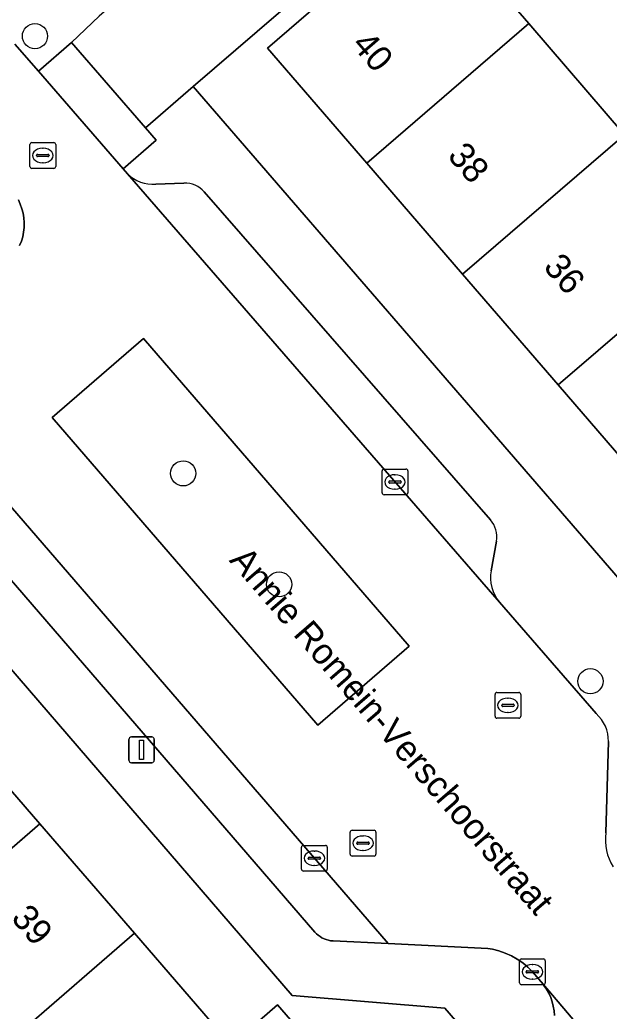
# Model space of a CAD drawing. Extents: x 160304 to 160955, y 383684 to 384161.
# Drawn here: x 160439.02 to 160461.92, y 384055.67 to 384094.2 of the extents above; entities that cross this region are included whole.
import ezdxf

# ---------------------------------------------------------------- set-up
doc = ezdxf.new("R2010")
doc.units = 0
for name, color, linetype in [('IMGEO_Boom', 7, 'Continuous'), ('IMGEO_Erf', 7, 'Continuous'), ('IMGEO_Kolk', 7, 'Continuous'), ('IMGEO_Lichtmast', 7, 'Continuous'), ('IMGEO_Openbare_ruimte_label', 7, 'Continuous'), ('IMGEO_Pand', 7, 'Continuous'), ('IMGEO_Pand_nummerreeks', 7, 'Continuous'), ('IMGEO_Parkeervlak_open', 7, 'Continuous'), ('IMGEO_Rijbaan_lokaal_open', 7, 'Continuous'), ('IMGEO_Rioolput', 7, 'Continuous'), ('IMGEO_Voetpad_open', 7, 'Continuous')]:
    doc.layers.add(name, color=color, linetype=linetype)

msp = doc.modelspace()

# ---------------------------------------------------------------- linework, layer by layer
at = {"layer": 'IMGEO_Boom'}
for centre in [(160439.61, 384093.564), (160445.372, 384076.571), (160449.097, 384072.258), (160461.195, 384068.492)]:
    msp.add_circle(centre, 0.489, dxfattribs=at)
at = {"layer": 'IMGEO_Erf'}
for points in [[(160480.535, 384052.567), (160476.806, 384056.888), (160473.083, 384061.203), (160469.356, 384065.523), (160465.516, 384069.973), (160467.284, 384071.499), (160463.67, 384075.687), (160459.939, 384080.012), (160456.229, 384084.312), (160452.508, 384088.624), (160448.645, 384093.101), (160454.74, 384098.361), (160454.335, 384098.831), (160457.615, 384101.658), (160457.542, 384101.745), (160445.759, 384091.611), (160464.179, 384070.303), (160464.114, 384064.194), (160482.27, 384043.068)], [(160458.201, 384094.743), (160458.796, 384094.053), (160462.523, 384089.733), (160466.243, 384085.421), (160468.493, 384082.814), (160471.638, 384085.527), (160473.112, 384083.818), (160474.901, 384081.745), (160471.757, 384079.032), (160473.809, 384076.654), (160475.061, 384077.691), (160478.712, 384073.459), (160478.133, 384072.959), (160481.824, 384068.681), (160485.546, 384064.367), (160483.121, 384062.275), (160486.83, 384057.977)]]:
    msp.add_lwpolyline(points, dxfattribs=at)
msp.add_lwpolyline([(160431.035, 384077.833), (160428.673, 384075.798), (160432.433, 384071.455), (160436.115, 384067.202), (160439.796, 384062.95), (160443.478, 384058.697), (160447.238, 384054.354), (160449.036, 384055.91), (160453.642, 384050.589), (160458.283, 384045.229), (160461.083, 384041.994), (160464.755, 384045.129), (160455.536, 384055.791), (160449.608, 384056.274)], close=True, dxfattribs=at)
at = {"layer": 'IMGEO_Kolk'}
for p, q in [((160453.1, 384075.811), (160453.1, 384076.663)), ((160453.175, 384076.737), (160454.027, 384076.737)), ((160453.588, 384076.517), (160453.613, 384076.517)), ((160454.101, 384076.663), (160454.101, 384075.811)), ((160453.359, 384076.231), (160453.359, 384076.243)), ((160453.797, 384076.194), (160453.399, 384076.194)), ((160453.402, 384076.28), (160453.8, 384076.28)), ((160453.843, 384076.243), (160453.843, 384076.231)), ((160454.027, 384075.737), (160453.175, 384075.737)), ((160453.611, 384075.957), (160453.586, 384075.957)), ((160449.967, 384061.188), (160449.967, 384062.04)), ((160450.042, 384062.114), (160450.894, 384062.114)), ((160450.455, 384061.894), (160450.48, 384061.894)), ((160450.968, 384062.04), (160450.968, 384061.188)), ((160450.226, 384061.608), (160450.226, 384061.62)), ((160450.664, 384061.571), (160450.266, 384061.571)), ((160450.269, 384061.657), (160450.667, 384061.657)), ((160450.71, 384061.62), (160450.71, 384061.608)), ((160450.894, 384061.114), (160450.042, 384061.114)), ((160450.478, 384061.334), (160450.453, 384061.334)), ((160458.44, 384056.772), (160458.44, 384057.624)), ((160458.515, 384057.698), (160459.367, 384057.698)), ((160459.441, 384057.624), (160459.441, 384056.772)), ((160458.699, 384057.192), (160458.699, 384057.204)), ((160458.742, 384057.241), (160459.14, 384057.241)), ((160458.928, 384057.478), (160458.953, 384057.478)), ((160459.183, 384057.204), (160459.183, 384057.192)), ((160459.137, 384057.155), (160458.739, 384057.155)), ((160458.951, 384056.918), (160458.926, 384056.918)), ((160459.367, 384056.698), (160458.515, 384056.698))]:
    msp.add_line(p, q, dxfattribs=at)
for points in [[(160453.1, 384075.811), (160453.1, 384076.663)], [(160453.175, 384076.737), (160454.027, 384076.737)], [(160454.101, 384076.663), (160454.101, 384075.811)], [(160454.027, 384075.737), (160453.175, 384075.737)], [(160449.967, 384061.188), (160449.967, 384062.04)], [(160450.042, 384062.114), (160450.894, 384062.114)], [(160450.968, 384062.04), (160450.968, 384061.188)], [(160450.894, 384061.114), (160450.042, 384061.114)], [(160458.44, 384056.772), (160458.44, 384057.624)], [(160458.515, 384057.698), (160459.367, 384057.698)], [(160459.441, 384057.624), (160459.441, 384056.772)], [(160459.367, 384056.698), (160458.515, 384056.698)]]:
    msp.add_lwpolyline(points, dxfattribs=at)
for centre, radius, start, end in [((160453.177, 384076.661), 0.0765, 91.552, 178.448), ((160453.177, 384076.661), 0.0765, 91.552, 178.448), ((160454.025, 384076.661), 0.0765, 1.552, 88.448), ((160454.025, 384076.661), 0.0765, 1.552, 88.448), ((160453.399, 384076.24), 0.0403, 85.8775, 175.7526), ((160453.396, 384076.23), 0.0366, 178.938, 274.7102), ((160453.8, 384076.237), 0.043, 264.8664, 352.4533), ((160453.804, 384076.242), 0.0386, 1.7309, 96.639), ((160453.177, 384075.813), 0.0765, 181.552, 268.448), ((160453.177, 384075.813), 0.0765, 181.552, 268.448), ((160454.025, 384075.813), 0.0765, 271.552, 358.448), ((160454.025, 384075.813), 0.0765, 271.552, 358.448), ((160450.044, 384062.038), 0.0765, 91.552, 178.448), ((160450.044, 384062.038), 0.0765, 91.552, 178.448), ((160450.892, 384062.038), 0.0765, 1.552, 88.448), ((160450.892, 384062.038), 0.0765, 1.552, 88.448), ((160450.266, 384061.617), 0.0403, 85.8775, 175.7526), ((160450.263, 384061.607), 0.0366, 178.938, 274.7102), ((160450.667, 384061.614), 0.043, 264.8664, 352.4533), ((160450.671, 384061.619), 0.0386, 1.7309, 96.639), ((160450.044, 384061.19), 0.0765, 181.552, 268.448), ((160450.044, 384061.19), 0.0765, 181.552, 268.448), ((160450.892, 384061.19), 0.0765, 271.552, 358.448), ((160450.892, 384061.19), 0.0765, 271.552, 358.448), ((160458.517, 384057.622), 0.0765, 91.552, 178.448), ((160458.517, 384057.622), 0.0765, 91.552, 178.448), ((160459.365, 384057.622), 0.0765, 1.552, 88.448), ((160459.365, 384057.622), 0.0765, 1.552, 88.448), ((160458.739, 384057.201), 0.0403, 85.8775, 175.7526), ((160458.736, 384057.191), 0.0366, 178.938, 274.7102), ((160459.14, 384057.198), 0.043, 264.8664, 352.4533), ((160459.144, 384057.203), 0.0386, 1.7309, 96.639), ((160458.517, 384056.774), 0.0765, 181.552, 268.448), ((160458.517, 384056.774), 0.0765, 181.552, 268.448), ((160459.365, 384056.774), 0.0765, 271.552, 358.448), ((160459.365, 384056.774), 0.0765, 271.552, 358.448)]:
    msp.add_arc(centre, radius, start, end, dxfattribs=at)
for centre, major_axis, ratio, start_param, end_param in [((160453.587, 384076.237), (-0.387, 0.002), 0.722429, 4.712389, 7.853982), ((160453.612, 384076.237), (-0.39, 0.002), 0.717154, 1.570796, 4.712389), ((160450.454, 384061.614), (-0.387, 0.002), 0.722429, 4.712389, 7.853982), ((160450.479, 384061.614), (-0.39, 0.002), 0.717154, 1.570796, 4.712389), ((160458.927, 384057.198), (-0.387, 0.002), 0.722429, 4.712389, 7.853982), ((160458.952, 384057.198), (-0.39, 0.002), 0.717154, 1.570796, 4.712389)]:
    msp.add_ellipse(centre, major_axis=major_axis, ratio=ratio, start_param=start_param, end_param=end_param, dxfattribs=at)
at = {"layer": 'IMGEO_Lichtmast'}
for p, q in [((160443.257, 384065.427), (160443.257, 384066.227)), ((160443.257, 384066.227), (160443.257, 384065.427)), ((160443.357, 384066.327), (160444.147, 384066.327)), ((160444.147, 384066.327), (160443.357, 384066.327)), ((160444.247, 384066.227), (160444.247, 384065.427)), ((160444.247, 384065.427), (160444.247, 384066.227)), ((160444.147, 384065.327), (160443.357, 384065.327)), ((160443.357, 384065.327), (160444.147, 384065.327))]:
    msp.add_line(p, q, dxfattribs=at)
msp.add_lwpolyline([(160443.677, 384066.202), (160443.827, 384066.202), (160443.827, 384065.452), (160443.677, 384065.452), (160443.677, 384066.202)], dxfattribs=at)
for centre, start, end in [((160443.357, 384066.227), 90, 180), ((160443.357, 384066.227), 90, 180), ((160444.147, 384066.227), 0, 90), ((160444.147, 384066.227), 360, 90), ((160443.357, 384065.427), 180, 270), ((160443.357, 384065.427), 180, 270), ((160444.147, 384065.427), 270, 0), ((160444.147, 384065.427), 270, 0)]:
    msp.add_arc(centre, 0.1, start, end, dxfattribs=at)
at = {"layer": 'IMGEO_Pand'}
for points in [[(160458.796, 384094.053), (160458.201, 384094.743), (160456.528, 384096.682), (160459.613, 384099.339), (160457.615, 384101.658), (160454.335, 384098.831), (160454.74, 384098.361), (160448.645, 384093.101), (160452.508, 384088.624)], [(160458.796, 384094.053), (160452.508, 384088.624), (160456.229, 384084.312), (160462.523, 384089.733)], [(160466.243, 384085.421), (160462.523, 384089.733), (160456.229, 384084.312), (160459.939, 384080.012)], [(160466.243, 384085.421), (160459.939, 384080.012), (160463.67, 384075.687), (160470.03, 384081.15), (160473.112, 384083.818), (160471.638, 384085.527), (160468.493, 384082.814)], [(160436.115, 384067.202), (160430.253, 384062.126), (160433.934, 384057.873), (160439.796, 384062.95)], [(160437.615, 384053.621), (160443.478, 384058.697), (160439.796, 384062.95), (160433.934, 384057.873)], [(160447.238, 384054.354), (160443.478, 384058.697), (160437.615, 384053.621), (160441.756, 384048.838), (160443.491, 384050.34), (160443.602, 384050.436), (160443.223, 384050.875)], [(160447.717, 384045.459), (160453.642, 384050.589), (160449.036, 384055.91), (160447.238, 384054.354), (160443.223, 384050.875), (160443.602, 384050.436), (160443.491, 384050.34)]]:
    msp.add_lwpolyline(points, close=True, dxfattribs=at)
at = {"layer": 'IMGEO_Parkeervlak_open'}
for points in [[(160443.203, 384088.215), (160457.659, 384071.56)], [(160445.399, 384087.85), (160444.301, 384087.806)], [(160457.311, 384074.767), (160446.192, 384087.508)], [(160457.335, 384072.788), (160457.542, 384073.932)], [(160472.741, 384040.954), (160459.355, 384056.713), (160459.387, 384056.672), (160459.488, 384056.524), (160459.577, 384056.367), (160459.651, 384056.203), (160459.71, 384056.033), (160459.753, 384055.858), (160459.781, 384055.68), (160459.793, 384055.501)]]:
    msp.add_lwpolyline(points, dxfattribs=at)
for points in [[(160450.6, 384066.79), (160454.152, 384069.858), (160443.825, 384081.814), (160440.273, 384078.746)], [(160453.335, 384058.295), (160435.453, 384078.998), (160435.184, 384076.979), (160435.176, 384076.891), (160435.176, 384076.802), (160435.183, 384076.713), (160435.199, 384076.626), (160435.222, 384076.54), (160435.253, 384076.457), (160435.292, 384076.377), (160435.337, 384076.3), (160435.389, 384076.228), (160435.418, 384076.193), (160450.49, 384058.744), (160450.551, 384058.679), (160450.617, 384058.62), (160450.689, 384058.567), (160450.764, 384058.521), (160450.844, 384058.481), (160450.927, 384058.449), (160451.013, 384058.424), (160451.1, 384058.408), (160451.188, 384058.399), (160451.198, 384058.398)]]:
    msp.add_lwpolyline(points, close=True, dxfattribs=at)
for centre, radius, start, end in [((160444.208, 384089.233), 1.43, 225.3937, 273.746), ((160445.438, 384086.849), 1.001, 41.1249, 92.2166), ((160456.552, 384074.108), 1.005, 349.9323, 40.9956), ((160458.815, 384072.522), 1.503, 169.7966, 219.764)]:
    msp.add_arc(centre, radius, start, end, dxfattribs=at)
at = {"layer": 'IMGEO_Rijbaan_lokaal_open'}
for points in [[(160478.766, 384112.396), (160474.284, 384112.752), (160470.92, 384112.993), (160467.431, 384113.243), (160464.253, 384113.464), (160463.586, 384112.912), (160461.96, 384111.509), (160459.428, 384109.325), (160456.688, 384106.961), (160453.36, 384104.073), (160450.825, 384101.886), (160448.136, 384099.566), (160446.601, 384098.234), (160443.56, 384095.599), (160442.844, 384094.981), (160442.101, 384094.34), (160441.031, 384093.311), (160443.904, 384090.001), (160445.759, 384091.611), (160457.542, 384101.745), (160463.283, 384106.683), (160464.817, 384108.006), (160465.206, 384108.28)], [(160457.659, 384071.56), (160443.203, 384088.215), (160443.038, 384088.405), (160439.747, 384092.196), (160438.831, 384093.257)], [(160438.965, 384087.196), (160439.042, 384087.029), (160439.103, 384086.857), (160439.149, 384086.679), (160439.178, 384086.498), (160439.192, 384086.315), (160439.189, 384086.132), (160439.169, 384085.949), (160439.134, 384085.769), (160439.082, 384085.593), (160439.015, 384085.422)], [(160435.453, 384078.998), (160453.335, 384058.295), (160457.205, 384058.11), (160457.388, 384058.078), (160457.64, 384058.015), (160457.886, 384057.929), (160458.122, 384057.821), (160458.348, 384057.693), (160458.562, 384057.545), (160458.761, 384057.379), (160458.945, 384057.195), (160459.355, 384056.713), (160472.741, 384040.954)], [(160461.416, 384067.232), (160457.659, 384071.56)], [(160461.792, 384062.602), (160461.895, 384066.145)]]:
    msp.add_lwpolyline(points, dxfattribs=at)
msp.add_lwpolyline([(160440.273, 384078.746), (160443.825, 384081.814), (160454.152, 384069.858), (160450.6, 384066.79)], close=True, dxfattribs=at)
for centre, radius, start, end in [((160460.479, 384066.17), 1.417, 358.9923, 48.5702), ((160463.828, 384062.342), 2.053, 172.7108, 211.2365)]:
    msp.add_arc(centre, radius, start, end, dxfattribs=at)
at = {"layer": 'IMGEO_Rioolput'}
for p, q in [((160439.415, 384088.499), (160439.415, 384089.351)), ((160439.49, 384089.425), (160440.342, 384089.425)), ((160439.903, 384089.205), (160439.928, 384089.205)), ((160440.416, 384089.351), (160440.416, 384088.499)), ((160439.674, 384088.919), (160439.674, 384088.931)), ((160440.112, 384088.882), (160439.714, 384088.882)), ((160439.717, 384088.968), (160440.115, 384088.968)), ((160440.158, 384088.931), (160440.158, 384088.919)), ((160440.342, 384088.425), (160439.49, 384088.425)), ((160439.926, 384088.645), (160439.901, 384088.645)), ((160457.488, 384067.129), (160457.488, 384067.981)), ((160457.563, 384068.055), (160458.415, 384068.055)), ((160458.489, 384067.981), (160458.489, 384067.129)), ((160457.79, 384067.598), (160458.188, 384067.598)), ((160457.976, 384067.835), (160458.001, 384067.835)), ((160457.747, 384067.549), (160457.747, 384067.561)), ((160458.185, 384067.512), (160457.787, 384067.512)), ((160457.999, 384067.275), (160457.974, 384067.275)), ((160458.231, 384067.561), (160458.231, 384067.549)), ((160458.415, 384067.055), (160457.563, 384067.055)), ((160451.858, 384061.772), (160451.858, 384062.624)), ((160451.933, 384062.698), (160452.785, 384062.698)), ((160452.859, 384062.624), (160452.859, 384061.772)), ((160452.117, 384062.192), (160452.117, 384062.204)), ((160452.16, 384062.241), (160452.558, 384062.241)), ((160452.346, 384062.478), (160452.371, 384062.478)), ((160452.601, 384062.204), (160452.601, 384062.192)), ((160452.555, 384062.155), (160452.157, 384062.155)), ((160452.369, 384061.918), (160452.344, 384061.918)), ((160452.785, 384061.698), (160451.933, 384061.698))]:
    msp.add_line(p, q, dxfattribs=at)
for points in [[(160439.415, 384088.499), (160439.415, 384089.351)], [(160439.49, 384089.425), (160440.342, 384089.425)], [(160440.416, 384089.351), (160440.416, 384088.499)], [(160440.342, 384088.425), (160439.49, 384088.425)], [(160457.488, 384067.129), (160457.488, 384067.981)], [(160457.563, 384068.055), (160458.415, 384068.055)], [(160458.489, 384067.981), (160458.489, 384067.129)], [(160458.415, 384067.055), (160457.563, 384067.055)], [(160451.858, 384061.772), (160451.858, 384062.624)], [(160451.933, 384062.698), (160452.785, 384062.698)], [(160452.859, 384062.624), (160452.859, 384061.772)], [(160452.785, 384061.698), (160451.933, 384061.698)]]:
    msp.add_lwpolyline(points, dxfattribs=at)
for centre, radius, start, end in [((160439.492, 384089.349), 0.0765, 91.552, 178.448), ((160439.492, 384089.349), 0.0765, 91.552, 178.448), ((160440.34, 384089.349), 0.0765, 1.552, 88.448), ((160440.34, 384089.349), 0.0765, 1.552, 88.448), ((160439.714, 384088.928), 0.0403, 85.8775, 175.7526), ((160439.711, 384088.918), 0.0366, 178.938, 274.7102), ((160440.115, 384088.925), 0.043, 264.8664, 352.4533), ((160440.119, 384088.93), 0.0386, 1.7309, 96.639), ((160439.492, 384088.501), 0.0765, 181.552, 268.448), ((160439.492, 384088.501), 0.0765, 181.552, 268.448), ((160440.34, 384088.501), 0.0765, 271.552, 358.448), ((160440.34, 384088.501), 0.0765, 271.552, 358.448), ((160457.565, 384067.979), 0.0765, 91.552, 178.448), ((160457.565, 384067.979), 0.0765, 91.552, 178.448), ((160458.413, 384067.979), 0.0765, 1.552, 88.448), ((160458.413, 384067.979), 0.0765, 1.552, 88.448), ((160457.787, 384067.558), 0.0403, 85.8775, 175.7526), ((160458.192, 384067.56), 0.0386, 1.7309, 96.639), ((160457.784, 384067.548), 0.0366, 178.938, 274.7102), ((160458.188, 384067.555), 0.043, 264.8664, 352.4533), ((160457.565, 384067.131), 0.0765, 181.552, 268.448), ((160457.565, 384067.131), 0.0765, 181.552, 268.448), ((160458.413, 384067.131), 0.0765, 271.552, 358.448), ((160458.413, 384067.131), 0.0765, 271.552, 358.448), ((160451.935, 384062.622), 0.0765, 91.552, 178.448), ((160451.935, 384062.622), 0.0765, 91.552, 178.448), ((160452.783, 384062.622), 0.0765, 1.552, 88.448), ((160452.783, 384062.622), 0.0765, 1.552, 88.448), ((160452.157, 384062.201), 0.0403, 85.8775, 175.7526), ((160452.154, 384062.191), 0.0366, 178.938, 274.7102), ((160452.558, 384062.198), 0.043, 264.8664, 352.4533), ((160452.562, 384062.203), 0.0386, 1.7309, 96.639), ((160451.935, 384061.774), 0.0765, 181.552, 268.448), ((160451.935, 384061.774), 0.0765, 181.552, 268.448), ((160452.783, 384061.774), 0.0765, 271.552, 358.448), ((160452.783, 384061.774), 0.0765, 271.552, 358.448)]:
    msp.add_arc(centre, radius, start, end, dxfattribs=at)
for centre, major_axis, ratio, start_param, end_param in [((160439.902, 384088.925), (-0.387, 0.002), 0.722429, 4.712389, 7.853982), ((160439.927, 384088.925), (-0.39, 0.002), 0.717154, 1.570796, 4.712389), ((160457.975, 384067.555), (-0.387, 0.002), 0.722429, 4.712389, 7.853982), ((160458, 384067.555), (-0.39, 0.002), 0.717154, 1.570796, 4.712389), ((160452.345, 384062.198), (-0.387, 0.002), 0.722429, 4.712389, 7.853982), ((160452.37, 384062.198), (-0.39, 0.002), 0.717154, 1.570796, 4.712389)]:
    msp.add_ellipse(centre, major_axis=major_axis, ratio=ratio, start_param=start_param, end_param=end_param, dxfattribs=at)
at = {"layer": 'IMGEO_Voetpad_open'}
for points in [[(160438.831, 384093.257), (160439.747, 384092.196), (160441.031, 384093.311), (160442.101, 384094.34)], [(160445.759, 384091.611), (160443.904, 384090.001), (160444.322, 384089.52), (160443.038, 384088.405), (160443.203, 384088.215)], [(160477.506, 384043.391), (160479.686, 384040.851), (160482.27, 384043.068), (160464.114, 384064.194), (160464.179, 384070.303), (160445.759, 384091.611)], [(160444.301, 384087.806), (160445.399, 384087.85)], [(160446.192, 384087.508), (160457.311, 384074.767)], [(160439.015, 384085.422), (160439.082, 384085.593), (160439.134, 384085.769), (160439.169, 384085.949), (160439.189, 384086.132), (160439.192, 384086.315), (160439.178, 384086.498), (160439.149, 384086.679), (160439.103, 384086.857), (160439.042, 384087.029), (160438.965, 384087.196)], [(160431.035, 384077.833), (160449.608, 384056.274), (160455.536, 384055.791), (160464.755, 384045.129)], [(160459.793, 384055.501), (160459.781, 384055.68), (160459.753, 384055.858), (160459.71, 384056.033), (160459.651, 384056.203), (160459.577, 384056.367), (160459.488, 384056.524), (160459.387, 384056.672), (160459.355, 384056.713), (160458.945, 384057.195), (160458.761, 384057.379), (160458.562, 384057.545), (160458.348, 384057.693), (160458.122, 384057.821), (160457.886, 384057.929), (160457.64, 384058.015), (160457.388, 384058.078), (160457.205, 384058.11), (160453.335, 384058.295), (160451.198, 384058.398), (160451.188, 384058.399), (160451.1, 384058.408), (160451.013, 384058.424), (160450.927, 384058.449), (160450.844, 384058.481), (160450.764, 384058.521), (160450.689, 384058.567), (160450.617, 384058.62), (160450.551, 384058.679), (160450.49, 384058.744), (160435.418, 384076.193)], [(160457.542, 384073.932), (160457.335, 384072.788)], [(160457.659, 384071.56), (160461.416, 384067.232)], [(160461.895, 384066.145), (160461.792, 384062.602)]]:
    msp.add_lwpolyline(points, dxfattribs=at)
msp.add_lwpolyline([(160441.031, 384093.311), (160439.747, 384092.196), (160443.038, 384088.405), (160444.322, 384089.52), (160443.904, 384090.001)], close=True, dxfattribs=at)
for centre, radius, start, end in [((160444.208, 384089.233), 1.43, 225.3937, 273.746), ((160445.438, 384086.849), 1.001, 41.1249, 92.2166), ((160456.552, 384074.108), 1.005, 349.9323, 40.9956), ((160458.815, 384072.522), 1.503, 169.7966, 219.764), ((160460.479, 384066.17), 1.417, 358.9923, 48.5702), ((160463.828, 384062.342), 2.053, 172.7108, 211.2365)]:
    msp.add_arc(centre, radius, start, end, dxfattribs=at)

# ---------------------------------------------------------------- texts
at = {"layer": 'IMGEO_Openbare_ruimte_label'}
msp.add_text('Annie Romein-Verschoorstraat', height=1, rotation=310.8249, dxfattribs=at).set_placement((160447.132, 384073.174))
at = {"layer": 'IMGEO_Pand_nummerreeks'}
for s, rotation, p in [('40', 310.7888, (160451.879, 384093.21)), ('38', 310.7888, (160455.606, 384088.89)), ('36', 310.7888, (160459.332, 384084.571)), ('39', 310.8861, (160438.648, 384059.265))]:
    msp.add_text(s, height=1, rotation=rotation, dxfattribs=at).set_placement(p)

doc.saveas('drawing.dxf')
